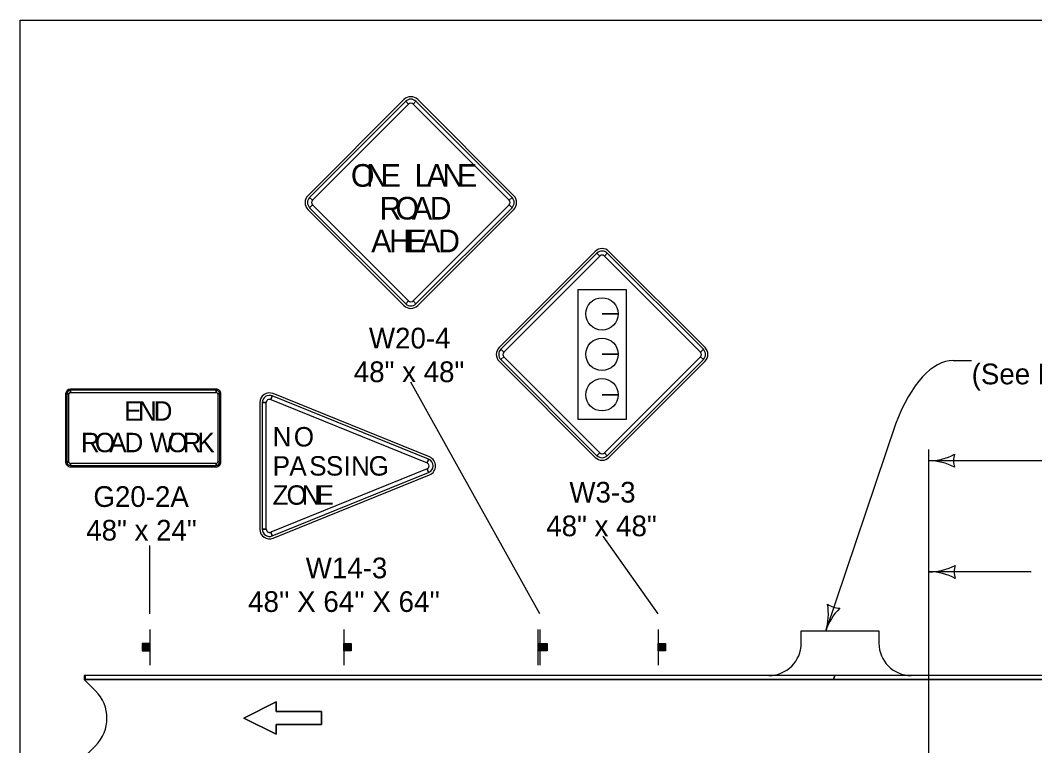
# Model space of a CAD drawing. Extents: x -2134934 to -2122394, y -2140205 to -2137036.
# Drawn here: x -2130232 to -2129448, y -2137596 to -2137036 of the extents above; entities that cross this region are included whole.
import ezdxf

# ---------------------------------------------------------------- set-up
doc = ezdxf.new("R2010")
doc.units = 0
for name, color, linetype in [('Barrier', 7, 'Continuous'), ('BridgeSuperStructureExisting', 7, 'Continuous'), ('Default', 7, 'Continuous'), ('DsnShtPlotIdentification', 7, 'Continuous'), ('DsnShtPlotShape', 7, 'Continuous')]:
    doc.layers.add(name, color=color, linetype=linetype)

msp = doc.modelspace()

# ---------------------------------------------------------------- linework, layer by layer
at = {"layer": 'Barrier'}
for p, q in [((-2129935.51, -2137097.19), (-2130009.75, -2137171.44)), ((-2129934.18, -2137098.52), (-2129931.97, -2137100.73)), ((-2129928.44, -2137100.73), (-2129926.23, -2137098.52)), ((-2129850.65, -2137171.44), (-2129924.9, -2137097.19)), ((-2130006.22, -2137174.97), (-2130008.43, -2137172.76)), ((-2129851.98, -2137172.76), (-2129854.19, -2137174.97)), ((-2130009.75, -2137182.04), (-2129935.51, -2137256.29)), ((-2130008.43, -2137180.72), (-2130006.22, -2137178.51)), ((-2129924.9, -2137256.29), (-2129850.65, -2137182.04)), ((-2129854.19, -2137178.51), (-2129851.98, -2137180.72)), ((-2129787.7, -2137214.53), (-2129861.95, -2137288.78)), ((-2129786.37, -2137215.86), (-2129784.17, -2137218.06)), ((-2129780.63, -2137218.06), (-2129778.42, -2137215.86)), ((-2129702.85, -2137288.78), (-2129777.09, -2137214.53)), ((-2129931.97, -2137252.76), (-2129934.18, -2137254.96)), ((-2129926.23, -2137254.96), (-2129928.44, -2137252.76)), ((-2129769.99, -2137262.75), (-2129782.49, -2137262.75)), ((-2129782.49, -2137262.75), (-2129769.99, -2137262.75)), ((-2129858.41, -2137292.31), (-2129860.62, -2137290.1)), ((-2129860.62, -2137298.06), (-2129858.41, -2137295.85)), ((-2129769.99, -2137294), (-2129782.49, -2137294)), ((-2129782.49, -2137294), (-2129769.99, -2137294)), ((-2129704.18, -2137290.1), (-2129706.38, -2137292.31)), ((-2129706.38, -2137295.85), (-2129704.18, -2137298.06)), ((-2129861.95, -2137299.38), (-2129787.7, -2137373.63)), ((-2129777.09, -2137373.63), (-2129702.85, -2137299.38)), ((-2130196.92, -2137324.64), (-2130196.92, -2137377.14)), ((-2130195.99, -2137324.64), (-2130194.42, -2137324.64)), ((-2130080.67, -2137320.89), (-2130193.17, -2137320.89)), ((-2130193.17, -2137323.39), (-2130193.17, -2137321.82)), ((-2130080.67, -2137321.82), (-2130080.67, -2137323.39)), ((-2130079.42, -2137324.64), (-2130077.86, -2137324.64)), ((-2130076.92, -2137377.14), (-2130076.92, -2137324.64)), ((-2130038.48, -2137329.01), (-2130037.31, -2137326.11)), ((-2129915.78, -2137373.25), (-2130036.61, -2137324.37)), ((-2129769.99, -2137325.25), (-2129782.49, -2137325.25)), ((-2129782.49, -2137325.25), (-2129769.99, -2137325.25)), ((-2130046.92, -2137331.32), (-2130046.92, -2137429.07)), ((-2130045.04, -2137331.32), (-2130041.92, -2137331.32)), ((-2129784.17, -2137370.09), (-2129786.37, -2137372.3)), ((-2129778.42, -2137372.3), (-2129780.63, -2137370.09)), ((-2130194.42, -2137377.14), (-2130195.99, -2137377.14)), ((-2130193.17, -2137379.95), (-2130193.17, -2137378.39)), ((-2130193.17, -2137380.89), (-2130080.67, -2137380.89)), ((-2130080.67, -2137378.39), (-2130080.67, -2137379.95)), ((-2130077.86, -2137377.14), (-2130079.42, -2137377.14)), ((-2129916.48, -2137374.98), (-2129917.66, -2137377.88)), ((-2130036.61, -2137436.03), (-2129915.78, -2137387.15)), ((-2129917.66, -2137382.52), (-2129916.48, -2137385.41)), ((-2130041.92, -2137429.07), (-2130045.04, -2137429.07)), ((-2130037.31, -2137434.29), (-2130038.48, -2137431.39))]:
    msp.add_line(p, q, dxfattribs=at)
for points in [[(-2129934.18, -2137098.52), (-2130008.43, -2137172.76), (-2130006.22, -2137174.97), (-2129931.97, -2137100.73), (-2129934.18, -2137098.52)], [(-2129851.98, -2137172.76), (-2129926.23, -2137098.52), (-2129928.44, -2137100.73), (-2129854.19, -2137174.97), (-2129851.98, -2137172.76)], [(-2130008.43, -2137180.72), (-2129934.18, -2137254.96), (-2129931.97, -2137252.76), (-2130006.22, -2137178.51), (-2130008.43, -2137180.72)], [(-2129926.23, -2137254.96), (-2129851.98, -2137180.72), (-2129854.19, -2137178.51), (-2129928.44, -2137252.76), (-2129926.23, -2137254.96)], [(-2129786.37, -2137215.86), (-2129860.62, -2137290.1), (-2129858.41, -2137292.31), (-2129784.17, -2137218.06), (-2129786.37, -2137215.86)], [(-2129704.18, -2137290.1), (-2129778.42, -2137215.86), (-2129780.63, -2137218.06), (-2129706.38, -2137292.31), (-2129704.18, -2137290.1)], [(-2129763.67, -2137244.13), (-2129801.13, -2137244.13), (-2129801.13, -2137344.02), (-2129763.67, -2137344.02), (-2129763.67, -2137244.13)], [(-2129860.62, -2137298.06), (-2129786.37, -2137372.3), (-2129784.17, -2137370.09), (-2129858.41, -2137295.85), (-2129860.62, -2137298.06)], [(-2129778.42, -2137372.3), (-2129704.18, -2137298.06), (-2129706.38, -2137295.85), (-2129780.63, -2137370.09), (-2129778.42, -2137372.3)], [(-2130195.99, -2137324.64), (-2130195.99, -2137377.14), (-2130194.42, -2137377.14), (-2130194.42, -2137324.64), (-2130195.99, -2137324.64)], [(-2130080.67, -2137321.82), (-2130193.17, -2137321.82), (-2130193.17, -2137323.39), (-2130080.67, -2137323.39), (-2130080.67, -2137321.82)], [(-2130077.86, -2137377.14), (-2130077.86, -2137324.64), (-2130079.42, -2137324.64), (-2130079.42, -2137377.14), (-2130077.86, -2137377.14)], [(-2129916.48, -2137374.98), (-2130037.31, -2137326.11), (-2130038.48, -2137329.01), (-2129917.66, -2137377.88), (-2129916.48, -2137374.98)], [(-2130045.04, -2137331.32), (-2130045.04, -2137429.07), (-2130041.92, -2137429.07), (-2130041.92, -2137331.32), (-2130045.04, -2137331.32)], [(-2130193.17, -2137379.95), (-2130080.67, -2137379.95), (-2130080.67, -2137378.39), (-2130193.17, -2137378.39), (-2130193.17, -2137379.95)], [(-2130037.31, -2137434.29), (-2129916.48, -2137385.41), (-2129917.66, -2137382.52), (-2130038.48, -2137431.39), (-2130037.31, -2137434.29)]]:
    msp.add_lwpolyline(points, close=True, dxfattribs=at)
for centre in [(-2129782.49, -2137262.75), (-2129782.49, -2137294), (-2129782.49, -2137325.25)]:
    msp.add_circle(centre, 12.5, dxfattribs=at)
for centre, radius, start, end in [((-2129930.2, -2137102.5), 7.5, 44.99999, 134.99974), ((-2129930.2, -2137102.5), 5.62, 44.99999, 134.99974), ((-2129930.2, -2137102.5), 2.5, 44.99999, 134.99974), ((-2130004.45, -2137176.74), 7.5, 134.99974, 224.99995), ((-2130004.45, -2137176.74), 5.62, 134.99974, 224.99995), ((-2130004.45, -2137176.74), 2.5, 134.99974, 224.99995), ((-2129855.96, -2137176.74), 2.5, 315.00016, 44.9998), ((-2129855.96, -2137176.74), 5.62, 315.00016, 44.9998), ((-2129855.96, -2137176.74), 7.5, 315.00016, 44.9998), ((-2129782.4, -2137219.83), 7.5, 44.99999, 134.99974), ((-2129782.4, -2137219.83), 5.62, 44.99999, 134.99974), ((-2129782.4, -2137219.83), 2.5, 44.99999, 134.99974), ((-2129930.2, -2137250.99), 7.5, 224.99995, 315.00016), ((-2129930.2, -2137250.99), 5.62, 224.99995, 315.00016), ((-2129930.2, -2137250.99), 2.5, 224.99995, 315.00016), ((-2129856.64, -2137294.08), 7.5, 134.99974, 224.99995), ((-2129856.64, -2137294.08), 5.62, 134.99974, 224.99995), ((-2129856.64, -2137294.08), 2.5, 134.99974, 224.99995), ((-2129708.15, -2137294.08), 2.5, 315.00016, 44.9998), ((-2129708.15, -2137294.08), 5.62, 315.00016, 44.9998), ((-2129708.15, -2137294.08), 7.5, 315.00016, 44.9998), ((-2130193.17, -2137324.64), 3.75, 90.00021, 179.99985), ((-2130193.17, -2137324.64), 2.81, 90.00021, 179.99985), ((-2130193.17, -2137324.64), 1.25, 90.00021, 179.99985), ((-2130080.67, -2137324.64), 3.75, 0, 90.00021), ((-2130080.67, -2137324.64), 2.81, 0, 90.00021), ((-2130080.67, -2137324.64), 1.25, 0, 90.00021), ((-2130039.42, -2137331.32), 7.5, 67.97571, 179.99985), ((-2130039.42, -2137331.32), 5.62, 67.97571, 179.99985), ((-2130039.42, -2137331.32), 2.5, 67.97571, 179.99985), ((-2129918.59, -2137380.2), 7.5, 292.02456, 67.97598), ((-2129782.4, -2137368.32), 7.5, 224.99995, 315.00016), ((-2129782.4, -2137368.32), 5.62, 224.99995, 315.00016), ((-2129782.4, -2137368.32), 2.5, 224.99995, 315.00016), ((-2130193.17, -2137377.14), 3.75, 179.99985, 270.00006), ((-2130193.17, -2137377.14), 2.81, 179.99985, 270.00006), ((-2130193.17, -2137377.14), 1.25, 179.99985, 270.00006), ((-2130080.67, -2137377.14), 3.75, 270.00006, 0.00027), ((-2130080.67, -2137377.14), 2.81, 270.00006, 0.00027), ((-2130080.67, -2137377.14), 1.25, 270.00006, 0.00027), ((-2129918.59, -2137380.2), 2.5, 292.02456, 67.97541), ((-2129918.59, -2137380.2), 5.62, 292.02456, 67.97541), ((-2130039.42, -2137429.07), 7.5, 179.99985, 292.02456), ((-2130039.42, -2137429.07), 5.62, 179.99985, 292.02456), ((-2130039.42, -2137429.07), 2.5, 179.99985, 292.02456)]:
    msp.add_arc(centre, radius, start, end, dxfattribs=at)
at = {"layer": 'BridgeSuperStructureExisting'}
for p, q in [((-2129511.1, -2137298.84), (-2129496.88, -2137298.84)), ((-2129830.55, -2137494.5), (-2129930.2, -2137315.49)), ((-2129555.83, -2137347.98), (-2129609.64, -2137507.67)), ((-2129530.12, -2137367.55), (-2129530.12, -2137605.16)), ((-2129305.21, -2137376.23), (-2129530.12, -2137376.23)), ((-2129739.15, -2137494.5), (-2129781.5, -2137434.54)), ((-2130131.95, -2137494.5), (-2130131.95, -2137441.62)), ((-2129450.84, -2137462.08), (-2129529.62, -2137462.08)), ((-2130131.95, -2137506.66), (-2130131.95, -2137534.16)), ((-2129981.95, -2137506.66), (-2129981.95, -2137534.16)), ((-2129831.95, -2137506.66), (-2129831.95, -2137534.16)), ((-2129830.55, -2137506.66), (-2129830.55, -2137534.16)), ((-2129739.15, -2137506.66), (-2129739.15, -2137534.16)), ((-2130137.28, -2137517.52), (-2130137.28, -2137523.11)), ((-2130136.96, -2137523.11), (-2130136.96, -2137517.52)), ((-2130136.73, -2137517.52), (-2130136.73, -2137523.11)), ((-2130136.41, -2137523.11), (-2130136.41, -2137517.52)), ((-2130136.19, -2137517.52), (-2130136.21, -2137523.11)), ((-2130135.78, -2137523.11), (-2130135.76, -2137517.52)), ((-2130135.55, -2137517.52), (-2130135.55, -2137523.11)), ((-2130135.12, -2137523.11), (-2130135.12, -2137517.52)), ((-2130134.75, -2137517.52), (-2130134.75, -2137523.11)), ((-2130134.43, -2137523.11), (-2130134.41, -2137517.52)), ((-2130134.2, -2137517.52), (-2130134.2, -2137523.11)), ((-2130133.94, -2137523.11), (-2130133.94, -2137517.52)), ((-2130133.6, -2137517.52), (-2130133.6, -2137523.11)), ((-2130133.4, -2137523.11), (-2130133.4, -2137517.52)), ((-2130133.17, -2137517.52), (-2130133.17, -2137523.11)), ((-2130132.91, -2137523.11), (-2130132.91, -2137517.52)), ((-2130132.65, -2137517.52), (-2130132.65, -2137523.11)), ((-2130132.36, -2137523.11), (-2130132.36, -2137517.52)), ((-2129981.54, -2137523.11), (-2129981.54, -2137517.52)), ((-2129981.26, -2137517.52), (-2129981.26, -2137523.11)), ((-2129980.99, -2137523.11), (-2129980.99, -2137517.52)), ((-2129980.73, -2137517.52), (-2129980.73, -2137523.11)), ((-2129980.51, -2137523.11), (-2129980.51, -2137517.52)), ((-2129980.3, -2137517.52), (-2129980.3, -2137523.11)), ((-2129979.96, -2137523.11), (-2129979.96, -2137517.52)), ((-2129979.7, -2137517.52), (-2129979.7, -2137523.11)), ((-2129979.47, -2137523.11), (-2129979.49, -2137517.52)), ((-2129979.16, -2137517.52), (-2129979.16, -2137523.11)), ((-2129978.78, -2137523.11), (-2129978.78, -2137517.52)), ((-2129978.35, -2137517.52), (-2129978.35, -2137523.11)), ((-2129978.12, -2137523.11), (-2129978.14, -2137517.52)), ((-2129977.71, -2137517.52), (-2129977.69, -2137523.11)), ((-2129977.49, -2137523.11), (-2129977.49, -2137517.52)), ((-2129977.17, -2137517.52), (-2129977.17, -2137523.11)), ((-2129976.94, -2137523.11), (-2129976.94, -2137517.52)), ((-2129976.62, -2137517.52), (-2129976.62, -2137523.11)), ((-2129831.54, -2137523.11), (-2129831.54, -2137517.52)), ((-2129831.26, -2137517.52), (-2129831.26, -2137523.11)), ((-2129830.99, -2137523.11), (-2129830.99, -2137517.52)), ((-2129830.73, -2137517.52), (-2129830.73, -2137523.11)), ((-2129830.51, -2137523.11), (-2129830.51, -2137517.52)), ((-2129830.3, -2137517.52), (-2129830.3, -2137523.11)), ((-2129830.14, -2137523.11), (-2129830.14, -2137517.52)), ((-2129829.96, -2137523.11), (-2129829.96, -2137517.52)), ((-2129829.86, -2137517.52), (-2129829.86, -2137523.11)), ((-2129829.7, -2137517.52), (-2129829.7, -2137523.11)), ((-2129829.6, -2137523.11), (-2129829.6, -2137517.52)), ((-2129829.47, -2137523.11), (-2129829.49, -2137517.52)), ((-2129829.33, -2137517.52), (-2129829.33, -2137523.11)), ((-2129829.16, -2137517.52), (-2129829.16, -2137523.11)), ((-2129829.11, -2137523.11), (-2129829.11, -2137517.52)), ((-2129828.9, -2137517.52), (-2129828.9, -2137523.11)), ((-2129828.78, -2137523.11), (-2129828.78, -2137517.52)), ((-2129828.57, -2137523.11), (-2129828.57, -2137517.52)), ((-2129828.35, -2137517.52), (-2129828.35, -2137523.11)), ((-2129828.3, -2137517.52), (-2129828.3, -2137523.11)), ((-2129828.12, -2137523.11), (-2129828.14, -2137517.52)), ((-2129828.08, -2137523.11), (-2129828.1, -2137517.52)), ((-2129827.76, -2137517.52), (-2129827.76, -2137523.11)), ((-2129827.71, -2137517.52), (-2129827.69, -2137523.11)), ((-2129827.49, -2137523.11), (-2129827.49, -2137517.52)), ((-2129827.38, -2137523.11), (-2129827.38, -2137517.52)), ((-2129827.17, -2137517.52), (-2129827.17, -2137523.11)), ((-2129826.95, -2137517.52), (-2129826.95, -2137523.11)), ((-2129826.94, -2137523.11), (-2129826.94, -2137517.52)), ((-2129826.73, -2137523.11), (-2129826.75, -2137517.52)), ((-2129826.62, -2137517.52), (-2129826.62, -2137523.11)), ((-2129826.32, -2137517.52), (-2129826.3, -2137523.11)), ((-2129826.09, -2137523.11), (-2129826.09, -2137517.52)), ((-2129825.77, -2137517.52), (-2129825.77, -2137523.11)), ((-2129825.55, -2137523.11), (-2129825.55, -2137517.52)), ((-2129825.23, -2137517.52), (-2129825.23, -2137523.11)), ((-2129738.74, -2137523.11), (-2129738.74, -2137517.52)), ((-2129738.46, -2137517.52), (-2129738.46, -2137523.11)), ((-2129738.2, -2137523.11), (-2129738.2, -2137517.52)), ((-2129737.93, -2137517.52), (-2129737.93, -2137523.11)), ((-2129737.71, -2137523.11), (-2129737.71, -2137517.52)), ((-2129737.5, -2137517.52), (-2129737.5, -2137523.11)), ((-2129737.16, -2137523.11), (-2129737.16, -2137517.52)), ((-2129736.9, -2137517.52), (-2129736.9, -2137523.11)), ((-2129736.68, -2137523.11), (-2129736.7, -2137517.52)), ((-2129736.36, -2137517.52), (-2129736.36, -2137523.11)), ((-2129735.98, -2137523.11), (-2129735.98, -2137517.52)), ((-2129735.55, -2137517.52), (-2129735.55, -2137523.11)), ((-2129735.33, -2137523.11), (-2129735.35, -2137517.52)), ((-2129734.91, -2137517.52), (-2129734.9, -2137523.11)), ((-2129734.69, -2137523.11), (-2129734.69, -2137517.52)), ((-2129734.37, -2137517.52), (-2129734.37, -2137523.11)), ((-2129734.15, -2137523.11), (-2129734.15, -2137517.52)), ((-2129733.83, -2137517.52), (-2129733.83, -2137523.11)), ((-2130182.57, -2137545.16), (-2130173.79, -2137553.95)), ((-2128680.12, -2137545.16), (-2130182.57, -2137545.16)), ((-2130182.57, -2137545.16), (-2130173.78, -2137553.95)), ((-2129543.56, -2137542.16), (-2129653.56, -2137542.16)), ((-2130173.78, -2137596.37), (-2130191.36, -2137613.95))]:
    msp.add_line(p, q, dxfattribs=at)
for points in [[(-2129628.56, -2137517.16), (-2129628.56, -2137507.67), (-2129568.56, -2137507.67), (-2129568.56, -2137517.16)], [(-2130034.3, -2137579.99), (-2130034.3, -2137587.49), (-2130059.3, -2137574.99), (-2130034.3, -2137562.49), (-2130034.3, -2137569.99), (-2129999.3, -2137569.99), (-2129999.3, -2137579.99), (-2130034.3, -2137579.99)]]:
    msp.add_lwpolyline(points, dxfattribs=at)
for points in [[(-2130132.05, -2137523.11), (-2130132.05, -2137517.48), (-2130137.67, -2137517.48), (-2130137.67, -2137523.11)], [(-2129981.86, -2137523.11), (-2129981.86, -2137517.48), (-2129976.23, -2137517.48), (-2129976.23, -2137523.11)], [(-2129831.86, -2137523.11), (-2129831.86, -2137517.48), (-2129826.23, -2137517.48), (-2129826.23, -2137523.11)], [(-2129830.46, -2137523.11), (-2129830.46, -2137517.48), (-2129824.83, -2137517.48), (-2129824.83, -2137523.11)], [(-2129739.06, -2137523.11), (-2129739.06, -2137517.48), (-2129733.43, -2137517.48), (-2129733.43, -2137523.11)], [(-2129999.3, -2137579.99), (-2129999.3, -2137569.99), (-2130034.3, -2137569.99), (-2130034.3, -2137562.49), (-2130059.3, -2137574.99), (-2130034.3, -2137587.49), (-2130034.3, -2137579.99)]]:
    msp.add_lwpolyline(points, close=True, dxfattribs=at)
for centre, radius, start, end in [((-2129529.62, -2137419.58), 42.5, 270, 298.07249), ((-2129493.99, -2137462.08), 16.42, 162.26665, 197.73335), ((-2129529.62, -2137504.58), 42.5, 61.92751, 90), ((-2129653.56, -2137517.16), 25, 270, 360), ((-2129543.56, -2137517.16), 25, 180, 270), ((-2130195, -2137575.16), 30, 315, 45), ((-2130195, -2137575.16), 30, 315, 45)]:
    msp.add_arc(centre, radius, start, end, dxfattribs=at)
msp.add_ellipse((-2129511.1, -2137511.77), major_axis=(0, 212.93), ratio=0.328743, start_param=0, end_param=0.693162, dxfattribs=at)
at = {"layer": 'Default'}
msp.add_lwpolyline([(-2130231.95, -2137035.95), (-2127096.96, -2137035.95), (-2127096.96, -2139045.94), (-2130231.95, -2139045.94)], close=True, dxfattribs=at)
at = {"layer": 'DsnShtPlotIdentification'}
for p, q in [((-2128680.12, -2137542.16), (-2130182.57, -2137542.16)), ((-2130182.57, -2137542.16), (-2130182.57, -2137545.16)), ((-2129602.5, -2137542.16), (-2130182.57, -2137542.16)), ((-2128680.12, -2137545.16), (-2130182.57, -2137545.16)), ((-2130182.57, -2137545.16), (-2129603.51, -2137545.16)), ((-2130181.95, -2137542.16), (-2130181.95, -2137545.16)), ((-2129602.5, -2137542.16), (-2129603.51, -2137545.16)), ((-2129603.51, -2137545.16), (-2129602.5, -2137542.16)), ((-2129603.51, -2137545.16), (-2129329.62, -2137545.16)), ((-2129329.62, -2137542.16), (-2129602.5, -2137542.16))]:
    msp.add_line(p, q, dxfattribs=at)
msp.add_lwpolyline([(-2130182.37, -2137545.16), (-2128872.37, -2137545.16)], dxfattribs=at)
at = {"layer": 'DsnShtPlotShape'}
for centre, radius, start, end in [((-2129530.12, -2137333.73), 42.5, 270, 298.07249), ((-2129494.48, -2137376.23), 16.42, 162.26665, 197.73335), ((-2129530.12, -2137418.73), 42.5, 61.92751, 90), ((-2129650.07, -2137494.6), 42.5, 342.08492, 10.15741), ((-2129569.2, -2137520.74), 42.5, 134.01243, 162.08492), ((-2129598.67, -2137473.76), 16.42, 234.35157, 269.81827)]:
    msp.add_arc(centre, radius, start, end, dxfattribs=at)

# ---------------------------------------------------------------- texts
at = {"layer": 'Barrier'}
for s, height, p in [('O', 17.5, (-2129976.49, -2137164.55)), ('N', 17.5, (-2129964.71, -2137164.55)), ('E', 17.5, (-2129953.49, -2137164.55)), ('L', 17.5, (-2129927.24, -2137164.55)), ('A', 17.5, (-2129918.04, -2137164.55)), ('N', 17.5, (-2129905.77, -2137164.55)), ('E', 17.5, (-2129894.54, -2137164.55)), ('R', 17.5, (-2129954.38, -2137189.87)), ('O', 17.5, (-2129942.09, -2137189.87)), ('A', 17.5, (-2129929.25, -2137189.87)), ('D', 17.5, (-2129915.6, -2137189.87)), ('A', 17.5, (-2129960.82, -2137215.18)), ('H', 17.5, (-2129946.95, -2137215.18)), ('E', 17.5, (-2129933.74, -2137215.18)), ('A', 17.5, (-2129923.02, -2137215.18)), ('D', 17.5, (-2129909.16, -2137215.18)), ('W20-4', 16, (-2129962.57, -2137289.49)), ('48" x 48"', 16, (-2129974.27, -2137315.49)), ('E', 15, (-2130151.6, -2137345.26)), ('N', 15, (-2130140.98, -2137345.26)), ('D', 15, (-2130128.89, -2137345.26)), ('N', 15, (-2130036.95, -2137365.2)), ('O', 15, (-2130020.61, -2137365.2)), ('R', 15, (-2130185.06, -2137369.64)), ('O', 15, (-2130174.38, -2137369.64)), ('A', 15, (-2130163.22, -2137369.64)), ('D', 15, (-2130151.36, -2137369.64)), ('W', 15, (-2130131.91, -2137369.64)), ('O', 15, (-2130118.18, -2137369.64)), ('R', 15, (-2130106.41, -2137369.64)), ('K', 15, (-2130095.11, -2137369.64)), ('P', 15, (-2130036.95, -2137387.7)), ('A', 15, (-2130024.06, -2137387.7)), ('S', 15, (-2130008.71, -2137387.7)), ('S', 15, (-2129995.82, -2137387.7)), ('I', 15, (-2129982.22, -2137387.7)), ('N', 15, (-2129976.36, -2137387.7)), ('G', 15, (-2129962.77, -2137387.7)), ('G20-2A', 16, (-2130175.45, -2137411.89)), ('Z', 15, (-2130036.95, -2137410.2)), ('O', 15, (-2130026.21, -2137410.2)), ('N', 15, (-2130014.38, -2137410.2)), ('E', 15, (-2130003.02, -2137410.2)), ('W3-3', 16, (-2129807.69, -2137408.54)), ('48" x 48"', 16, (-2129825.57, -2137434.54)), ('48" x 24"', 16, (-2130180.99, -2137437.89)), ('W14-3', 16, (-2130011.41, -2137467.03)), ("48'' X 64'' X 64''", 16, (-2130055.9, -2137493.03))]:
    msp.add_text(s, height=height, dxfattribs=at).set_placement(p)
at = {"layer": 'BridgeSuperStructureExisting'}
msp.add_text('(See Exeter Ave Advanced Signing on J.5)', height=16, dxfattribs=at).set_placement((-2129496.88, -2137317.19))

doc.saveas('drawing.dxf')
